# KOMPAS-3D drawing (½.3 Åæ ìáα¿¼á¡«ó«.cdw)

Views: Вид 1
Referenced files in C:\Program Files\ASCON\KOMPAS-3D V10\Sys\: SPDS.lcs, Graphic.lcs
Referenced files in \\F-server\проектирование\Проекты\РЗА и ПА Тюменские РС\4. Проект\ЭП\Туринская\Рабочая документация\: план располодения оборудования на ПС.cdw
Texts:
  Текст на чертеже
  Размерные надписи
  Шероховатость
  Линия-выноска #1
  Линия-выноска #2
  Линия-выноска #3
  Отклонения формы и база
  Заголовок таблицы
  Ячейка таблицы
  Стрелка вида
  Обозначение изменения
  Фигурная скобка
  Номер узла
  Марка координационной оси
  VRCB
  Выносная надпись
  Обозначение узла
  Марка/позиционное обозначение с линией-выноской
  Марка/позиционное обозначение на линии
  Марка/позиционное обозначение без линии-выноски
  Лит-Масса-Масштаб
  Материал-Предприятие
  Title Specification
  Body Specification ( left align )
  Body Specificaton ( centered )
  Без имени
  Normal
  heading 1
  Знак Знак Знак Знак Знак Знак
  Verdana
  Body Text
  MS Sans Serif
  Txt
  Simplex
  TXT
  Обычный
  Термин
  Список определений
  Адрес
  Цитаты
  Форматированный
  Courier New
  Z-конец формы
  Z-начало формы
  Additional DXF text style 0
  Абзац Знак
  Body Text 3
  Title
  ТекстШаг1
  Шрифт 2.5
  Заголовки
  txt
  heading 2
  AGOpus
  footer
  Денис
  RUSTXT
  Обычный (веб)
  ООббыыччнныыйй
  Definition Term
  Definition List
  Address
  Blockquote
  Preformatted
  z-Bottom of Form
  z-Top of Form
  header
  NormalParagraphStyle
  ссылки
  Подпись в квадратике
  табл
  цепи
  Маркировка
  клеммы, контакты
  тексты табл
  Тексты. 3,2
  ЗОНА_привяз
  текст переноса
  ТТееррммиинн
  ССппииссоокк ооппррееддееллеенниийй
  ААддрреесс
  ЦЦииттааттыы
  ФФооррммааттиирроовваанннныыйй
  Z-ккооннеецц ффооррммыы
  Z-ннааччааллоо ффооррммыы
  GOST 2.304 type A
  rustxt
  heading 8
  heading 3
  heading 6
  heading 7
  russ
  heading 4
  heading 5
  heading 9
  HeliosLight
  Pa3
  Pa1
  Три с половиной
  style2
  Table Contents
  Table Heading
  ГОСТ_МНЕ
  ESK - Обозначение
  маркировка
  ISOCP
  ROMANS
  SIMPLEX
  Текст 3,5
  Tahoma
  текст табл
  Пояснения 2
  romans
  gif
  ISOCPEUR
  CM12
  Клеммник текст
  Пояснения
  Ссылки
  подписи
  Аппараты
  ячейка табл.
  Состав чартежа
  CM16+18
  FR5
  Subtitle
  CNBNDG+TimesNewRoman
  Courier New Cyr
  Normal (Web)
  romanc
  eskd1
  Pa15
  Pa18
  CC С?т?и?л?ь? П?о? ц?е?н?т?р?у?
  ошиновка
  лотки
  Демонтаж
  Топосъемка
  Примечания:
  1. Для нужд строительства (размещение задействованного в строительстве персонала, обеспечение
  электроэнергией) использовать временные мобильные инвентарные здания;
  2. При выполнении всех строительно-монтажных работ на площадке необходимо руководствоваться
  требованиями СНиП 12-03-2001 "Безопасность труда в строительстве. Общие требования",
  СНиП 12-04-2002 "Безопасность труда в строительстве. Строительное производство", а также
  ПОТ-РМ-016-2001/РД 153-34.0-03.150-00 "Межотраслевые правила по охране труда (правила
  безопасности) при эксплуатации электроустановок";
  3. Наружное освещение строительной площадки осуществляется за счет существующего освещения;
  4. Под временные сооружения (поз. II, III и IV) устраивается площадка из дорожных плит ПД 60-20 на
  щебеночном основании толщиной 15см;
  5. На период строительства для электроснабжения временных зданий и сооружений использовать ди-
  зельную электростанцию. Прокладку  кабеля от дизельной электростанции до вагончиков выполнить
  в воздушном исполнении в гофрированной трубе диаметром 30 мм, на вагончиках кабель закрепить
  скобами. Щиток временного электроснабжения навесить на стенку вагона-дома для отдыха рабочих;
  6. При выполнении монтажных работ использовать инвентарные лестницы и леса;
  7. На паспорте-стенде строительного объекта  должен быть план пожарной защиты с нанесенными
  строящимися и вспомогательными зданиями и сооружениями, въездами, подъездами, местонахождениями
  водоисточников, средств пожаротушения и связи (согласно ППБ-01-03 п.575);
  8. Условные обозначения см. 16/01-ПОС,л.1.
  9. Тонкой линией изображено существующее оборудование, замена которого проектом не
  предусматривается,  утолщенной - демонтируемое оборудование.
  Экспликация зданий и сооружений
  Номер
  на плане
  Постоянные здания и сооружения
  КРУН 10 кВ
  Трансформатор 1Т, маслоприемник
  Существующее
  Существующий
  Временные здания и сооружения
  III
  Вагон-дом для кратковременного отдых рабочих
  Уборная
  Дизельная электростанция
  Контейнеры для ТБО (0,75м 3 ) и жидких хоз.-быт.стоков(1м 3 )
  «Екатерина» 9,0х3,0
  Туалетная кабина "Люкс"
  ОАО ПКТИпромстрой
  h.забора 62.44
  h.забора 62.66
  кр.61.26
  н.пр.68.50
  h.забора 62.58
  н.пр.74.66
  н.пр.67.77
  н.пр.67.53
  h.забора 62.74
  н.пр.68.02
  н.пр.68.07
  скв.№4
  каб.лоток
  тр-р
  зру
  гр.
  КМУ ИНМАН ИМ-150
  K5LT_BASIC_RGB_0_0_255_THICK_0.6
  K5LT_BASIC_RGB_0_0_255_THICK_0.2
  K5LT_AXLED_RGB_255_128_0_SC_1_THICK_0.09
  POLYLINE_STYLE_0.18_RGB_168_80_0
  CONTI_RGB_0_0_0_THICK_0.18
  CONTI_RGB_51_51_51_THICK_0.18
  CONTI_RGB_51_51_51_THICK_0.4
  CONTI_RGB_0_0_0_THICK_0.4
  Стили документа
  Бортовой автомобиль КамАЗ 43114-027-02
  АТ ППР#010#0104
  ГИП
  Н.контр.
  Гл.спец.
  Провер.
  Разраб.
  Перезавод ВЛ на ПС Тюмень. Реконструкция устройств
  РЗ и ПА на обратных концах отходящих ВЛ,
  ВОЛС Тюменского ТПО
  ПС 110/10 кВ Нариманово
  Матвеев
  Ромин
  Шашерин
  Королева
  Микрюков
  Строительный генеральный план
  Общие технические условия на средний ремонт
Dimensions and other numbers on the sheet: 16/01-ПОД; 7; 2,5; 1,8; 2.5; 3,2_; 3.5; 3,2; 2,5 (контакты, клеммы); 3,2 (надписи); 3,2 (Зоны); 5; 2,5_01; 2,5_3; 3,5_01; 3,5_tabl; 5_заголовок; 2,3_; 3,2_зона не привяз; 3,5; 3.2 маркировка; 3,2 элементы; 3,2 линия; 3,2 таблица; 2,5 грязносинь; 2.5 курсив; 2.5_Э5_надписи; 2.5_Э5_ссылки; 2.5_кабель; 3.2; 2.5 надписи; 3 и 5; 5,0_белый_подчёркнутый; 3.2 фиол; 3.2 (текст); 1; 2; 10,6; 61.11; 60.94; 61.04; 60.85; 60.98; 60.79; 62.72; 63.28; 62.34; 61.74; 63.33; 63.98; 62.37; 63.23; 62.32; 62.08; 63.24; 63.25; 63.86; 60.82; 62.36; 62.98; 62.46; 62.86; 61.98; 62.90; 61.40; 61.46; 62.87; 61.78; 61.90; 61.19; 62.04; 62.52; 62.85; 63.10; 63.11; 61.55; 61.06; 60.88; 61.64; 62.99; 60.80; 62.25; 61.03; 61.49; 61.16; 60.99; 61.02; 61.05; 61.08; 60.96; 61.20; 626250; 1каб.10кВ; 60.56; 4; 05.13; 3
